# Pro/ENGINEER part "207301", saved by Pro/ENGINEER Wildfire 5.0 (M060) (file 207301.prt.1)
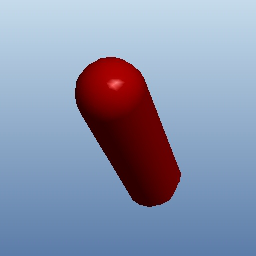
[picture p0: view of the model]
Units: PSOLunit; MM, KILOGRAM, SECS

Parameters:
  NN = "Series 515_5"
  NT = "Horizontal Handle Hold Down Action Clamps"
  NB = "207301"
  NBSYN = "$PN."
  LINA = "207301"
  PN = "207301"
  SUPPLIER = "DESTACO"
  ARTICLENO = "207301"
  BOMINFO = "207301"
  CREATOR = "CADENAS GmbH"

Other parameters: SURF_AREA, MASS

Other named items: COORD, DEF-PLANE-AXIS, DEF-PLANE-AXIS-INV, CS0, RUBBER_CP1_CSYS, TO_HANDLE_CSYS, CONN, MASS, RIGHT, TOP, FRONT, RUBBER_CP1_XPLN, RUBBER_CP1_YPLN, RUBBER_CP1_ZPLN, TO_HANDLE_XPLN, TO_HANDLE_YPLN, TO_HANDLE_ZPLN, RUBBER_CP1_ZAXS, TO_HANDLE_ZAXS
